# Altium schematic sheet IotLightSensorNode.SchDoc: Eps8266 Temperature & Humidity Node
size A4; Engineer: Evert; Revision: 1.0; SheetNumber: 1; SheetTotal: 1
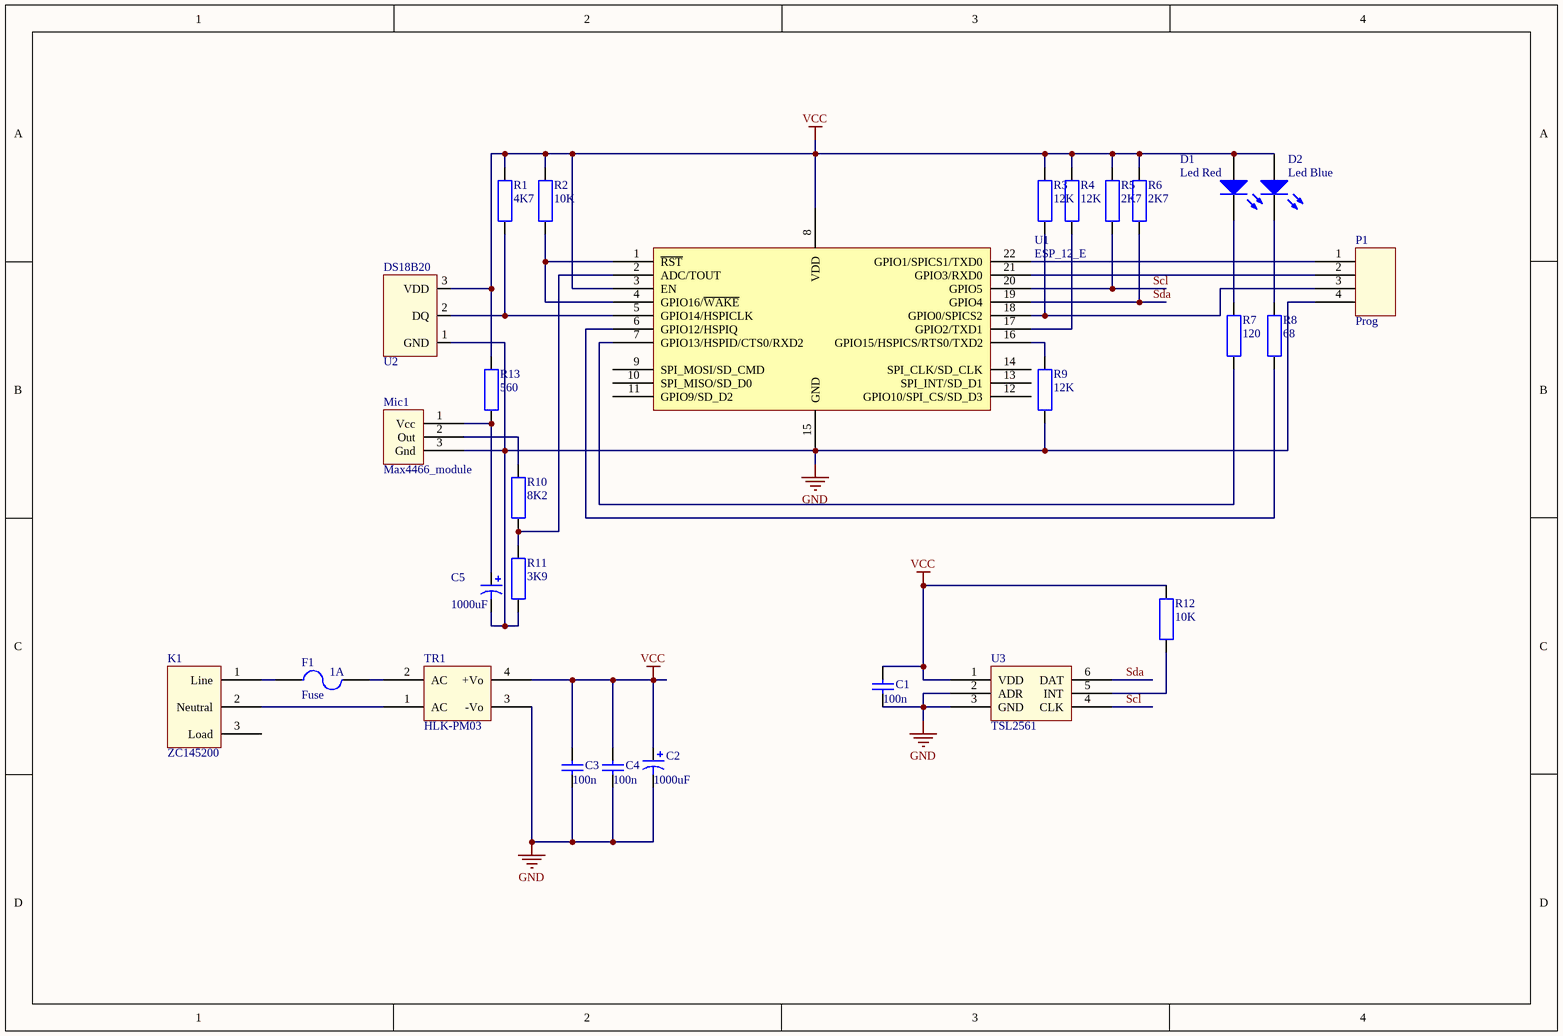
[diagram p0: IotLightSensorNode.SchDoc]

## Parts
C1  value 100n  [1608[0603]]  (hidden comment: Cap Semi)
C2  value 1000uF  [X]  (hidden comment: T491X)
C3  value 100n  [1608[0603]]  (hidden comment: Cap Semi)
C4  value 100n  [1608[0603]]  (hidden comment: Cap Semi)
C5  value 1000uF  [X]  (hidden comment: T491X)
D1  Led Red  [LED1608]
D2  Led Blue  [LED1608]
F1  Fuse  value 1A  [SmdFuse1808]
K1  ZC145200  [ZC145200]
Mic1  Max4466_module  [MAX446_Module]
P1  Prog  [Header4x1.27mm]
R1  value 4K7  [RES0603R]  (hidden comment: Resistor)
R2  value 10K  [RES0603R]  (hidden comment: Resistor)
R3  value 12K  [RES0603R]  (hidden comment: Resistor)
R4  value 12K  [RES0603R]  (hidden comment: Resistor)
R5  value 2K7  [RES0603R]  (hidden comment: Resistor)
R6  value 2K7  [RES0603R]  (hidden comment: Resistor)
R7  value 120  [RES0603R]  (hidden comment: Resistor)
R8  value 68  [RES0603R]  (hidden comment: Resistor)
R9  value 12K  [RES0603R]  (hidden comment: Resistor)
R10  value 8K2  [RES0603R]  (hidden comment: Resistor)
R11  value 3K9  [RES0603R]  (hidden comment: Resistor)
R12  value 10K  [RES0603R]  (hidden comment: Resistor)
R13  value 560  [RES0603R]  (hidden comment: Resistor)
TR1  HLK-PM03  [HLK-PM03]
U1  ESP_12_E  [ESP_12_E]
U2  DS18B20  [TO-92-AMMO]
U3  TSL2561  [DFN6-2x2]

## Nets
GND: C1.1 C2.2 C3.1 C4.1 C5.2 Mic1.3(Gnd) P1.4 R9.2 R11.2 TR1.3(-Vo) U1.15(GND) U2.1(GND) U3.2(ADR) U3.3(GND)
VCC: C1.2 C2.1 C3.2 C4.2 D1.1(A) D2.1(A) R1.1 R2.1 R3.1 R4.1 R5.1 R6.1 R12.1 R13.1 TR1.4(+Vo) U1.3(EN) U1.8(VDD) U2.3(VDD) U3.1(VDD)
Scl: R5.2 U1.20(GPIO5) U3.4(CLK)
Sda: R6.2 U1.19(GPIO4) U3.6(DAT)
NetC5_1: C5.1 Mic1.1(Vcc) R13.2
NetD1_2: D1.2(K) R7.1
NetD2_2: D2.2(K) R8.1
NetF1_1: F1.1 K1.1(Line)
NetF1_2: F1.2 TR1.2(AC)
NetK1_2: K1.2(Neutral) TR1.1(AC)
NetMic1_2: Mic1.2(Out) R10.1
NetP1_1: P1.1 U1.22(GPIO1/SPICS1/TXD0)
NetP1_2: P1.2 U1.21(GPIO3/RXD0)
NetP1_3: P1.3 R3.2 U1.18(GPIO0/SPICS2)
NetR1_2: R1.2 U1.5(GPIO14/HSPICLK) U2.2(DQ)
NetR2_2: R2.2 U1.1(~{RST}) U1.4(GPIO16/~{WAKE})
NetR4_2: R4.2 U1.17(GPIO2/TXD1)
NetR7_2: R7.2 U1.7(GPIO13/HSPID/CTS0/RXD2)
NetR8_2: R8.2 U1.6(GPIO12/HSPIQ)
NetR9_1: R9.1 U1.16(GPIO15/HSPICS/RTS0/TXD2)
NetR10_2: R10.2 R11.1 U1.2(ADC/TOUT)
NetR12_2: R12.2 U3.5(INT)

Not connected (* = marked no-connect by the designer): K1 3(Load); U1 9(SPI_MOSI/SD_CMD) 10(SPI_MISO/SD_D0) 11(GPIO9/SD_D2) 12(GPIO10/SPI_CS/SD_D3) 13(SPI_INT/SD_D1) 14(SPI_CLK/SD_CLK)

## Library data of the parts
C1 C3 C4 = Cap Semi: Capacitor (Semiconductor SIM Model)
C2 C5 = T491X: Solid Tantalum Chip Capacitor, Standard T491 Series - Industrial Grade; PCB_Layout: Round Glue Pad at 2.9 ±0.1mm in diameter at KEMET's option
D1 D2 = Led: pin to pad: 1>A 2>K
K1 = ZC145200: ZC145000 LightSensor
P1 = Header4x1.27mm
TR1 = HLK-PM03: Hi-Link HLK-PM03 3.3VDC/3W Power Module
U1 = ESP_12_E: ESP-12 Wi-Fi Module by AI-Thinker; IC: ESP8266-EX
U2 = DS18B20: Temp%20Sensor%20Digital%20Serial%20%281-Wire%29%203-Pin%20TO-92%20T/R; MP: DS18B20-SL+T&amp;R; MF: Maxim Integrated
